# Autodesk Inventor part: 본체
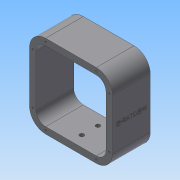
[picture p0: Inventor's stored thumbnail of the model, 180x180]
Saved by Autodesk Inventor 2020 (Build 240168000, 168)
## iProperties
Created: 2016-12
Part Number: 본체
Material: 알루미늄 6061
Document SubType Name: Modeling
Designer: mduedu
Density: 2.71 g/cm^3
Appearance: 기본값
Mass: 1192.15 g
Surface Area: 887.138 cm^2
Volume: 439.908 cm^3
Author: mduedu
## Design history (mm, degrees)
sketch "스케치1"
  geometry: L1 (-54, 50)-(-54, -44); L2 (-24, 80)-(70, 80); L3 (100, 50)-(100, -44); L4 (70, -74)-(-24, -74); A1 r 30 centre (-24, -44) between (-54, -44) and (-24, -74); A2 r 30 centre (70, 50) between (100, 50) and (70, 80); A3 r 30 centre (70, -44) between (70, -74) and (100, -44); A4 r 30 centre (-24, 50) between (-24, 80) and (-54, 50); 1 further point
  constraints: 8 end point, 8 point on circle, 8 tangent, 4 centre point, 3 equal radius, 2 perpendicular, 1 horizontal, 1 vertical
  dimensions: "d83" = 30 radius of A2; "d84" = 100 distance from line of L3 point (0, 0); "d85" = 154 distance between parallel lines of L4 L2; "d87" = 80 distance from line of point (0, 0) L2
extrude "돌출1" new body sketch "스케치1" stored distance "d3" = 70; taper "d4" = 0 deg
feature "쉘1" dims "d5" = 12
sketch "스케치10"
  geometry: 2 further points
  constraints: 1 coincident, 1 other
feature "엠보싱1" sketch "스케치10" dims "d61" = 0.5, "d62" = 0
sketch "스케치11"
  geometry: L1 (-42, -44)-(-42, 50) reference; L2 (-24, 68)-(70, 68) reference; L3 (88, 50)-(88, -44) reference; L4 (70, -62)-(-24, -62) reference; L5 (-24, -74)-(70, -74) reference; L6 (100, -44)-(100, 50) reference; L7 (70, 80)-(-24, 80) reference; L8 (-54, 50)-(-54, -44) reference; L9 (-24, 74)-(70, 74); L10 (94, 50)-(94, -44); L11 (70, -68)-(-24, -68); L12 (-48, -44)-(-48, 50); A1 r 18 centre (-24, -44) between (-42, -44) and (-24, -62) reference; A2 r 18 centre (-24, 50) between (-24, 68) and (-42, 50) reference; A3 r 18 centre (70, 50) between (88, 50) and (70, 68) reference; A4 r 18 centre (70, -44) between (70, -62) and (88, -44) reference; A5 r 30 centre (-24, -44) between (-54, -44) and (-24, -74) reference; A6 r 30 centre (70, -44) between (70, -74) and (100, -44) reference; A7 r 30 centre (70, 50) between (100, 50) and (70, 80) reference; A8 r 30 centre (-24, 50) between (-24, 80) and (-54, 50) reference; A9 r 24 centre (70, 50) between (94, 50) and (70, 74); A10 r 24 centre (70, -44) between (70, -68) and (94, -44); A11 r 24 centre (-24, -44) between (-48, -44) and (-24, -68); A12 r 24 centre (-24, 50) between (-24, 74) and (-48, 50); 8 further points
  constraints: 8 coincident, 8 end point, 8 point on circle, 4 centre point, 7 other
  dimensions: "d90" = 6 distance between parallel lines of L9 L7
hole "구멍3" sketch "스케치11" at (-24, 74), (-48, 50), (-48, -44), (-24, -68), (70, -68), (94, -44), (94, 50), (70, 74) diameter "d63" = 3.242; stored, may be unused: countersink angle "d67" = 90 deg, drill point angle "d69" = 120 deg; dims "d64" = 8.6, "d65" = 4, "d66" = 2, "d68" = 10.6
sketch "스케치12"
  geometry: L1 (24, -62)-(-70, -62) reference; L2 (-88, -44)-(-88, 50) reference; L3 (-70, 68)-(24, 68) reference; L4 (42, 50)-(42, -44) reference; L5 (54, -44)-(54, 50) reference; L6 (24, 80)-(-70, 80) reference; L7 (-100, 50)-(-100, -44) reference; L8 (-70, -74)-(24, -74) reference; L9 (-70, 74)-(24, 74); L10 (48, 50)-(48, -44); L11 (24, -68)-(-70, -68); L12 (-94, -44)-(-94, 50); A1 r 18 centre (24, -44) between (24, -62) and (42, -44) reference; A2 r 18 centre (-70, -44) between (-88, -44) and (-70, -62) reference; A3 r 18 centre (-70, 50) between (-70, 68) and (-88, 50) reference; A4 r 18 centre (24, 50) between (42, 50) and (24, 68) reference; A5 r 30 centre (24, -44) between (24, -74) and (54, -44) reference; A6 r 30 centre (24, 50) between (54, 50) and (24, 80) reference; A7 r 30 centre (-70, 50) between (-70, 80) and (-100, 50) reference; A8 r 30 centre (-70, -44) between (-100, -44) and (-70, -74) reference; A9 r 24 centre (24, 50) between (48, 50) and (24, 74); A10 r 24 centre (24, -44) between (24, -68) and (48, -44); A11 r 24 centre (-70, -44) between (-94, -44) and (-70, -68); A12 r 24 centre (-70, 50) between (-70, 74) and (-94, 50); 8 further points
  constraints: 8 coincident, 8 end point, 8 point on circle, 4 centre point, 7 other
  dimensions: "d91" = 6 distance between parallel lines of L9 L6
hole "구멍5" sketch "스케치12" at (-70, 74), (-94, 50), (-94, -44), (-70, -68), (24, -68), (48, -44), (48, 50), (24, 74) diameter "d70" = 3.242; stored, may be unused: countersink angle "d74" = 90 deg, drill point angle "d76" = 120 deg; dims "d71" = 8.6, "d72" = 4, "d73" = 2, "d75" = 10.6
sketch "스케치15"
  geometry: L1 (154.8, -35)-(-60.8, -35) reference; L2 (94, 0)-(0, 0) reference; L3 (0, -70)-(94, -70) reference; L4 (47, 0)-(47, -70); C1 r 4 at (47, -20); C2 r 4 at (47, -50); 1 further point
  constraints: 2 centre point, 2 end point, 2 midpoint, 1 point on line, 1 symmetric about line, 1 other
  dimensions: "d92" = 8 diameter of C1; "d93" = 15 distance from line of C1.centre L1
extrude "돌출6" cut sketch "스케치15" extent not by distance; stored distance "d94" = 10; taper "d95" = 0 deg
node "솔리드1"
node "투영된 루프3"
node "투영된 루프4"
